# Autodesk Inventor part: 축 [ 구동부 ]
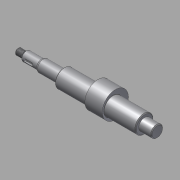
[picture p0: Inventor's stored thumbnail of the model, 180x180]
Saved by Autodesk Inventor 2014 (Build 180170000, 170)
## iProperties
Created: 2015-12
Part Number: 축 [ 구동부 ]
Document SubType Name: Modeling
Designer: mdu
Density: 7.86 g/cm^3
Material: 강철, 연강
Appearance: 강철
Mass: 489.709 g
Surface Area: 127.382 cm^2
Volume: 62.304 cm^3
Author: mdu
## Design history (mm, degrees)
sketch "스케치1"
  geometry: L1 (62, 100.9)-(62, 67.1) reference; L2 (51, 101.2)-(51, 84) reference; L3 (-51, 84)-(-51, 101.2) reference; L4 (-62, 67.1)-(-62, 100.9) reference; L5 (-51.6, 91.5)-(-61.4, 91.5) reference; L6 (51.6, 91.5)-(61.4, 91.5) reference; L7 (67, 84)-(-109, 84); L8 (-77, 64.201)-(-77, 103.799) reference; L9 (67, 84)-(67, 91.5); L10 (67, 91.5)-(51, 91.5); L11 (51, 91.5)-(51, 95.5); L12 (51, 95.5)-(-51, 95.5); L13 (-51, 95.5)-(-51, 91.5); L14 (-51, 91.5)-(-79, 91.5); L15 (-79, 91.5)-(-79, 90); L16 (-79, 90)-(-99, 90); L17 (-99, 90)-(-99, 87); L18 (-100.5, 88)-(-109, 88); L19 (-109, 88)-(-109, 84); L20 (-99, 87)-(-100.5, 87); L21 (-100.5, 87)-(-100.5, 88); 2 further points
  constraints: 32 end point, 7 parallel, 6 point on line, 5 perpendicular, 2 collinear, 2 horizontal, 1 midpoint, 4 other
  dimensions: "d0" = 5 distance from line of L7.start L1; "d2" = 2 distance between parallel lines of L15 L8; "d3" = 23 diameter of L12 L7; "d4" = 12 diameter of L16 L7; "d5" = 1.5 distance of L17.end L20.end; "d6" = 6 diameter of L20 L7; "d7" = 20 distance of L15.end L16.end; "d8" = 10 distance between parallel lines of L17 L19; "d9" = 8 diameter of L18 L7
revolve "회전1" sketch "스케치1" stored, may be unused: angle "d10" = 90 deg
sketch "스케치2"
  geometry: C1 r 11.5 at (84, 0) reference; C2 r 11.5 at (84, 0) reference; C3 r 16.5 at (87, 0); 1 further point
  constraints: 1 centre point, 1 horizontal alignment
  dimensions: "d11" = 33 diameter of C3; "d12" = 3 distance of C3.centre C1.centre
extrude "돌출1" join sketch "스케치2" stored distance "d13" = 22; taper "d14" = 0 deg
chamfer "모따기1" distance "d15" = 1; stored, may be unused: second distance "d16" = 2, angle "d17" = 45 deg
feature "스레드1" dims "d18" = 10, "d19" = 0
node "작업 평면1"
sketch "스케치3"
  geometry: L1 (-5, -2)-(3, -2); L2 (3, 2)-(-5, 2); L3 (-10, -5)-(-10, 5) reference; A1 r 2 centre (3, 0) between (3, -2) and (3, 2); A2 r 2 centre (-5, 0) between (-5, 2) and (-5, -2); 2 further points
  constraints: 4 end point, 4 point on circle, 4 tangent, 2 centre point, 1 horizontal, 1 horizontal alignment, 1 midpoint, 1 parallel
  dimensions: "d20" = 4 distance between parallel lines of L1 L2; "d21" = 12 dimension on A1 A2; "d22" = 3 distance edge to line of A2 L3
extrude "돌출2" cut sketch "스케치3" distance "d23" = 2.5; taper "d24" = 0 deg
fillet "모깎기1" dims "d25" = 0.3
fillet "모깎기2" dims "d26" = 3
node "솔리드1"
node "참조1"
node "참조2"
node "참조3"
node "참조4"
node "참조5"
node "투영된 루프1"
